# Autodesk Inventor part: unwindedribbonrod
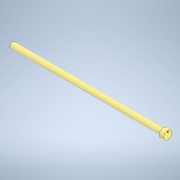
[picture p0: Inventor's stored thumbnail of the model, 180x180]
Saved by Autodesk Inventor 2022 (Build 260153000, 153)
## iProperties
Created: 2021-06
Part Number: unwindedribbonrod
Material: Generic
Document SubType Name: Modeling
Designer: Chimms
Density: 1 g/cm^3
Appearance: Default
Author: Chimms
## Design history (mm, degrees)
sketch "Sketch1"
  geometry: C1 r 5 at (0, 0); 1 further point
  constraints: 1 centre point, 1 coincident
  dimensions: "d0" = 10 diameter of C1
extrude "Extrusion1" new body sketch "Sketch1" distance "d1" = 270; taper "d2" = 0 deg
fillet "Fillet1" dims "d3" = 1
fillet "Fillet2" dims "d4" = 1
sketch "Sketch2"
  geometry: C1 r 7.5 at (0, 0); 1 further point
  constraints: 1 centre point, 1 coincident
  dimensions: "d5" = 15 diameter of C1
extrude "Extrusion2" join sketch "Sketch2" distance "d6" = 8; taper "d7" = 0 deg
sketch "Sketch3"
  geometry: C1 r 1.5 at (0, 5); 2 further points
  constraints: 1 centre point, 1 vertical alignment, 1 other
  dimensions: "d8" = 3 diameter of C1
extrude "Extrusion3" join sketch "Sketch3" distance "d9" = 0.25; taper "d10" = 0 deg
body "Solid1"
